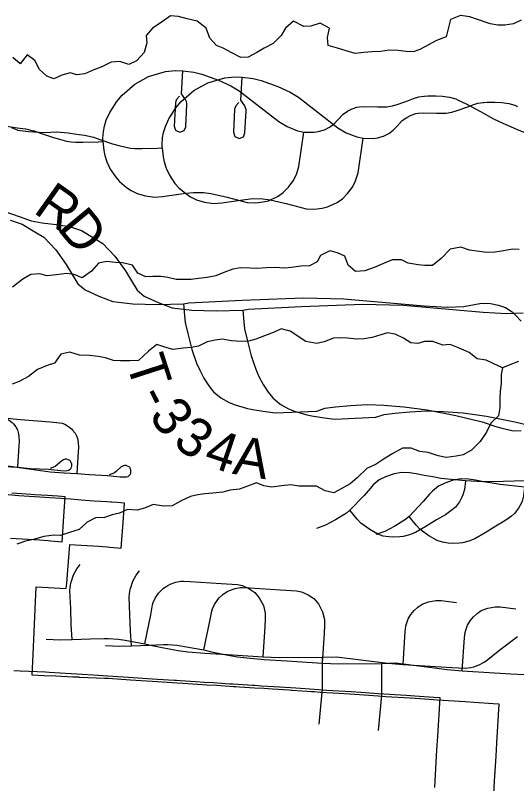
# Model space of a CAD drawing. Extents: x -38.2 to 41.9, y -4 to 24.9.
# Drawn here: x 7.758 to 8.49, y 18.257 to 19.38 of the extents above; entities that cross this region are included whole.
import ezdxf

# ---------------------------------------------------------------- set-up
doc = ezdxf.new("R2010")
doc.units = 0
for name, color, linetype in [('Default', 7, 'Continuous'), ('GM_X_County_Road', 7, 'Continuous'), ('GM_X_Minor_River', 7, 'Continuous'), ('GM_X_State_Location', 7, 'Continuous'), ('GM_X_Township_Road', 7, 'Continuous'), ('GM_X_Township_Road_Text', 7, 'Continuous')]:
    doc.layers.add(name, color=color, linetype=linetype)

msp = doc.modelspace()

# ---------------------------------------------------------------- linework, layer by layer
at = {"layer": 'Default'}
for points in [[(7.7507, 18.616), (7.7927, 18.6132), (7.8053, 18.6123), (7.8092, 18.6118), (7.8258, 18.6103), (7.8285, 18.6477), (7.8305, 18.6762), (7.8197, 18.677), (7.812, 18.6775), (7.8108, 18.6776), (7.8047, 18.678), (7.786, 18.6792), (7.7801, 18.6796), (7.7673, 18.6806), (7.7524, 18.6818)], [(8.3701, 18.2517), (8.3711, 18.2702), (8.3733, 18.3066), (8.3744, 18.326), (8.3778, 18.3826), (8.3688, 18.3832), (8.3412, 18.385), (8.3282, 18.3859), (8.2875, 18.3886), (8.2622, 18.3902), (8.2478, 18.3912), (8.2123, 18.3935), (8.2009, 18.3942), (8.167, 18.3965), (8.1594, 18.397), (8.135, 18.3986), (8.117, 18.3998), (8.1074, 18.4004), (8.1038, 18.4007), (8.0754, 18.4025), (8.0745, 18.4025), (8.0708, 18.4028), (8.0465, 18.4043), (8.0338, 18.4052), (8.0206, 18.406), (7.9984, 18.4074), (7.9932, 18.4078), (7.9895, 18.408), (7.9654, 18.4096), (7.9508, 18.4105), (7.9371, 18.4114), (7.9156, 18.4128), (7.9072, 18.4133), (7.8853, 18.4147), (7.8789, 18.4151), (7.8473, 18.4171), (7.8392, 18.4176), (7.8068, 18.4198), (7.8015, 18.42), (7.765, 18.4217), (7.7645, 18.4217), (7.7555, 18.4222)]]:
    msp.add_lwpolyline(points, dxfattribs=at)
at = {"layer": 'GM_X_County_Road'}
msp.add_lwpolyline([(8.4565, 18.2425), (8.4576, 18.261), (8.4598, 18.2974), (8.4609, 18.3168), (8.4643, 18.3734), (8.4553, 18.374), (8.4277, 18.3758), (8.4146, 18.3767), (8.374, 18.3794), (8.3487, 18.381), (8.3343, 18.382), (8.2987, 18.3843), (8.2874, 18.385), (8.2535, 18.3873), (8.2458, 18.3878), (8.2215, 18.3894), (8.2035, 18.3906), (8.1939, 18.3912), (8.1903, 18.3915), (8.1619, 18.3933), (8.161, 18.3934), (8.1573, 18.3936), (8.133, 18.3952), (8.1203, 18.396), (8.1071, 18.3968), (8.0848, 18.3983), (8.0797, 18.3986), (8.076, 18.3988), (8.0519, 18.4004), (8.0373, 18.4013), (8.0236, 18.4022), (8.002, 18.4036), (7.9937, 18.4041), (7.9718, 18.4055), (7.9654, 18.4059), (7.9338, 18.4079), (7.9257, 18.4084), (7.8933, 18.4106), (7.888, 18.4108), (7.8515, 18.4125), (7.851, 18.4126), (7.842, 18.413), (7.8415, 18.413), (7.8166, 18.4142), (7.7995, 18.4149), (7.7824, 18.4157), (7.7837, 18.4459), (7.7851, 18.4789), (7.7866, 18.512), (7.788, 18.5448), (7.8316, 18.5422), (7.833, 18.5499), (7.8344, 18.569), (7.8372, 18.6068), (7.8792, 18.604), (7.8917, 18.6031), (7.8957, 18.6026), (7.9123, 18.6011), (7.9149, 18.6385), (7.917, 18.667), (7.9061, 18.6678), (7.8985, 18.6683), (7.8973, 18.6684), (7.8912, 18.6688), (7.8725, 18.67), (7.8666, 18.6704), (7.8538, 18.6714), (7.8388, 18.6726), (7.824, 18.6737), (7.8078, 18.6748), (7.7932, 18.6758), (7.7779, 18.6768), (7.7629, 18.6778), (7.7625, 18.6779), (7.7473, 18.6789)], dxfattribs=at)
at = {"layer": 'GM_X_Minor_River'}
for points in [[(8.4962, 19.3727), (8.4849, 19.367), (8.4724, 19.3651), (8.4622, 19.3651), (8.4512, 19.367), (8.4327, 19.3735), (8.4213, 19.3773), (8.4077, 19.3795), (8.3933, 19.3735), (8.3895, 19.3598), (8.3869, 19.3484), (8.3729, 19.3428), (8.3619, 19.3371), (8.3483, 19.3299), (8.3385, 19.3265), (8.3282, 19.3268), (8.3169, 19.328), (8.3036, 19.3287), (8.2911, 19.3268), (8.2783, 19.3261), (8.2666, 19.3253), (8.2537, 19.3238), (8.2408, 19.3276), (8.2283, 19.3314), (8.2143, 19.3356), (8.2136, 19.347), (8.2162, 19.3606), (8.2026, 19.3682), (8.1893, 19.364), (8.1791, 19.3633), (8.164, 19.3709), (8.1519, 19.361), (8.1458, 19.35), (8.1341, 19.3382), (8.1212, 19.3318), (8.1103, 19.3254), (8.0974, 19.3185), (8.0868, 19.3182), (8.0739, 19.3246), (8.0611, 19.3314), (8.0512, 19.3356), (8.0417, 19.3462), (8.0361, 19.361), (8.0232, 19.3709), (8.0084, 19.3743), (7.9959, 19.3777), (7.9842, 19.3788), (7.9691, 19.3682), (7.9581, 19.3607), (7.9487, 19.35), (7.9494, 19.3394), (7.9456, 19.3254), (7.9343, 19.3133), (7.9233, 19.3076), (7.9104, 19.3121), (7.8976, 19.3114), (7.884, 19.3042), (7.8722, 19.3), (7.859, 19.2943), (7.8476, 19.2928), (7.8378, 19.2958), (7.8253, 19.292), (7.8136, 19.2867), (7.8034, 19.2905), (7.7928, 19.3004), (7.7859, 19.3137), (7.775, 19.322), (7.7647, 19.3087), (7.7541, 19.3182)], [(8.4934, 19.0374), (8.4835, 19.0378), (8.4703, 19.0355), (8.4582, 19.0336), (8.446, 19.0329), (8.4351, 19.0344), (8.4207, 19.0363), (8.4082, 19.0409), (8.3927, 19.0378), (8.3794, 19.0246), (8.3666, 19.0139), (8.3556, 19.0139), (8.3458, 19.0151), (8.3314, 19.0174), (8.3215, 19.0223), (8.3079, 19.0223), (8.2954, 19.017), (8.2814, 19.0113), (8.2682, 19.0064), (8.2546, 19.0056), (8.2436, 19.0147), (8.2387, 19.0276), (8.2281, 19.0326), (8.2167, 19.0356), (8.2035, 19.0288), (8.1986, 19.0193), (8.1872, 19.0136), (8.1743, 19.0132), (8.1611, 19.011), (8.1505, 19.0102), (8.1372, 19.0113), (8.1244, 19.0106), (8.1104, 19.0098), (8.1005, 19.0102), (8.0862, 19.0106), (8.0752, 19.0087), (8.0619, 19.0038), (8.0506, 18.9992), (8.0377, 18.9966), (8.0249, 18.9951), (8.0143, 18.9939), (8.0033, 18.9939), (7.9927, 18.9936), (7.9802, 18.9966), (7.97, 18.9981), (7.9586, 18.9981), (7.948, 18.9978), (7.9363, 19.0031), (7.9287, 19.0144), (7.9143, 19.0179), (7.9037, 19.0186), (7.8913, 19.0198), (7.8791, 19.0175), (7.8686, 19.0057), (7.8553, 18.9963), (7.8436, 19.0008), (7.8322, 19.0027), (7.8175, 19.0004), (7.8038, 18.9989), (7.7932, 19.002), (7.78, 19.0008), (7.7683, 18.994), (7.7535, 18.9823)], [(8.4923, 18.8739), (8.4821, 18.8698), (8.4692, 18.8648), (8.4556, 18.8709), (8.445, 18.8759), (8.4321, 18.8778), (8.4204, 18.8872), (8.4049, 18.8937), (8.3924, 18.8986), (8.3818, 18.8979), (8.3674, 18.9032), (8.3553, 18.9032), (8.3454, 18.9002), (8.3352, 18.9013), (8.3246, 18.9078), (8.3121, 18.9138), (8.3012, 18.9157), (8.2913, 18.9127), (8.2788, 18.9089), (8.2671, 18.907), (8.2557, 18.9066), (8.2425, 18.9078), (8.2323, 18.9085), (8.2221, 18.9082), (8.2084, 18.9025), (8.1978, 18.9002), (8.1819, 18.9032), (8.1592, 18.9184), (8.146, 18.9215), (8.1358, 18.9169), (8.1214, 18.9112), (8.1089, 18.9067), (8.0983, 18.9036), (8.0873, 18.9029), (8.073, 18.904), (8.0601, 18.9063), (8.0495, 18.9052), (8.0378, 18.9025), (8.0249, 18.8965), (8.0151, 18.8942), (8.0026, 18.8934), (7.9874, 18.8915), (7.9746, 18.8953), (7.9643, 18.8988), (7.9519, 18.8889), (7.9375, 18.8756), (7.9246, 18.8749), (7.9114, 18.8749), (7.9008, 18.8753), (7.8894, 18.8791), (7.8788, 18.8813), (7.866, 18.8825), (7.8512, 18.8832), (7.8372, 18.8874), (7.8239, 18.8844), (7.8149, 18.8715), (7.8039, 18.8681), (7.7899, 18.862), (7.777, 18.8518), (7.763, 18.8446), (7.7532, 18.8408)], [(8.4692, 18.8648), (8.4673, 18.855), (8.4669, 18.8425), (8.4658, 18.8303), (8.4651, 18.8205), (8.4651, 18.8064), (8.4632, 18.7943), (8.4522, 18.7837), (8.4458, 18.7708), (8.4363, 18.7571), (8.4238, 18.7446), (8.4117, 18.7378), (8.4015, 18.7355), (8.3868, 18.7336), (8.375, 18.7359), (8.3603, 18.7408), (8.3485, 18.7424), (8.3357, 18.7473), (8.3232, 18.7473), (8.3088, 18.7397), (8.2978, 18.7329), (8.2846, 18.7238), (8.271, 18.7177), (8.2566, 18.7041), (8.2464, 18.6954), (8.2335, 18.6878), (8.2225, 18.6821), (8.2101, 18.6851), (8.1972, 18.692), (8.1851, 18.6916), (8.1714, 18.692), (8.1601, 18.6939), (8.1465, 18.6924), (8.1321, 18.6901), (8.1207, 18.6924), (8.1098, 18.6969), (8.0965, 18.6916), (8.0848, 18.6875), (8.0712, 18.6859), (8.0606, 18.6829), (8.0462, 18.6814), (8.0341, 18.6806), (8.0239, 18.6791), (8.0133, 18.6769), (8, 18.6704), (7.9868, 18.6632), (7.9739, 18.6625), (7.9591, 18.6651), (7.9463, 18.6598), (7.9357, 18.6568), (7.9213, 18.6579), (7.9096, 18.6522), (7.899, 18.65), (7.8876, 18.6462), (7.8748, 18.6454), (7.8623, 18.6394), (7.8509, 18.6284), (7.8365, 18.6242), (7.8237, 18.6197), (7.8138, 18.6204), (7.7991, 18.6182), (7.7839, 18.614), (7.7722, 18.6113), (7.7597, 18.6072)]]:
    msp.add_lwpolyline(points, dxfattribs=at)
at = {"layer": 'GM_X_State_Location'}
msp.add_line((8.2927, 18.3936), (8.2927, 18.4328), dxfattribs=at)
for points in [[(7.8698, 19.2019), (7.8717, 19.2015), (7.8809, 19.1982), (7.8996, 19.1921), (7.9086, 19.1894), (7.9188, 19.1868), (7.9256, 19.1856), (7.9322, 19.1851), (7.9429, 19.185), (7.9649, 19.1855), (7.9719, 19.1862), (7.9719, 19.1909), (7.9727, 19.2005), (7.9741, 19.2083), (7.9768, 19.2171), (7.982, 19.2285), (7.9921, 19.2444), (7.9999, 19.2538), (8.0184, 19.27), (8.0388, 19.2809), (8.0635, 19.2881), (8.0782, 19.2896), (8.0888, 19.2893), (8.1047, 19.2875), (8.1166, 19.2844), (8.1408, 19.2757), (8.159, 19.2675), (8.1709, 19.2602), (8.2288, 19.2154), (8.2409, 19.2079), (8.2562, 19.2019), (8.2654, 19.2), (8.2804, 19.1999), (8.2864, 19.2006), (8.2954, 19.2032), (8.303, 19.2072), (8.3092, 19.2117), (8.315, 19.2177), (8.3227, 19.2262), (8.3293, 19.2304), (8.3357, 19.2338), (8.3425, 19.236), (8.346, 19.2367), (8.3532, 19.2371), (8.373, 19.2367), (8.3866, 19.2367), (8.3949, 19.238), (8.403, 19.2404), (8.4185, 19.2461), (8.4258, 19.2488), (8.4332, 19.2512), (8.4407, 19.2522), (8.4417, 19.2523)], [(8.084, 19.2524), (8.0795, 19.2472), (8.0784, 19.2449), (8.0779, 19.2425), (8.076, 19.2088), (8.0781, 19.2024), (8.0845, 19.1995), (8.0906, 19.2023), (8.0928, 19.2077), (8.0946, 19.2403), (8.0945, 19.2418), (8.0939, 19.2447), (8.0927, 19.2475), (8.087, 19.2557), (8.0888, 19.2893)], [(8.4417, 19.2523), (8.4465, 19.2526), (8.458, 19.2526), (8.468, 19.2522), (8.4781, 19.2506), (8.4872, 19.2482), (8.4908, 19.2465)], [(7.7518, 19.2157), (7.7613, 19.212), (7.7766, 19.2097), (7.8, 19.2084), (7.8184, 19.2096), (7.8347, 19.2081), (7.8469, 19.206), (7.8587, 19.2047), (7.8698, 19.2019)], [(7.9719, 19.1862), (7.9733, 19.173), (7.9749, 19.1654), (7.9778, 19.1562), (7.9827, 19.1459), (7.9907, 19.134), (7.9963, 19.1276), (8.0064, 19.1191), (8.0133, 19.1145), (8.022, 19.1103), (8.0339, 19.1066), (8.0477, 19.1049), (8.0591, 19.1055), (8.0896, 19.1101), (8.1038, 19.1118), (8.119, 19.1117), (8.1298, 19.1101), (8.1533, 19.1046), (8.1825, 19.0971), (8.1946, 19.0964), (8.2059, 19.0978), (8.2135, 19.0996), (8.2277, 19.1064), (8.2353, 19.1117), (8.2429, 19.1192), (8.2498, 19.1288), (8.2545, 19.1377), (8.2581, 19.1495), (8.2654, 19.2)], [(7.7421, 19.093), (7.7634, 19.0855), (7.7809, 19.0793), (7.797, 19.0766), (7.8174, 19.0741), (7.8366, 19.0712), (7.854, 19.0653), (7.8728, 19.0542), (7.8855, 19.0461), (7.9031, 19.028), (7.9185, 19.0063), (7.9257, 18.9944), (7.9353, 18.9781), (7.9458, 18.9694), (7.966, 18.9603), (7.9864, 18.9525), (8.0154, 18.9491), (8.0516, 18.9479), (8.0896, 18.9489), (8.0974, 18.9503), (8.1754, 18.9544), (8.2649, 18.9576), (8.3239, 18.9563), (8.441, 18.9462), (8.475, 18.9439), (8.4993, 18.9452)], [(8.0896, 18.9489), (8.0911, 18.9318), (8.0922, 18.9218), (8.0961, 18.9057), (8.102, 18.8822), (8.1087, 18.8625), (8.1134, 18.8522), (8.1196, 18.8402), (8.1267, 18.8292), (8.1337, 18.8206), (8.1444, 18.8117), (8.1566, 18.8047), (8.1653, 18.8013), (8.1833, 18.7962), (8.1907, 18.7947), (8.2058, 18.7922), (8.2236, 18.7898), (8.2843, 18.7924), (8.2962, 18.7963), (8.3118, 18.7983), (8.3335, 18.8003), (8.3584, 18.8017), (8.3824, 18.8007), (8.4117, 18.7987), (8.4457, 18.794), (8.4873, 18.7857), (8.5259, 18.7767)], [(7.7056, 18.7974), (7.7363, 18.7927), (7.7545, 18.7903), (7.7651, 18.7894), (7.8083, 18.7859), (7.8182, 18.7849), (7.8258, 18.7837), (7.8299, 18.7823), (7.8351, 18.7792), (7.8394, 18.7757), (7.8413, 18.7738), (7.8449, 18.7691), (7.8471, 18.7651), (7.8484, 18.7612), (7.8494, 18.7559), (7.8497, 18.7478), (7.8492, 18.7418), (7.8473, 18.7104)], [(7.7466, 18.7216), (7.7666, 18.7187), (7.8083, 18.7129), (7.8289, 18.7114), (7.8473, 18.7104), (7.866, 18.7087), (7.8922, 18.7073), (7.9105, 18.7056), (7.918, 18.7052), (7.9201, 18.7053), (7.9222, 18.706), (7.924, 18.7073), (7.9254, 18.709), (7.9262, 18.7107), (7.9264, 18.712), (7.9264, 18.7146), (7.9257, 18.7171), (7.9246, 18.7193), (7.9237, 18.7201), (7.9216, 18.7212), (7.9193, 18.7219), (7.9169, 18.7219), (7.9158, 18.7217), (7.9145, 18.7212), (7.9122, 18.7198), (7.9052, 18.7137), (7.9022, 18.7115), (7.8989, 18.7098), (7.8948, 18.7082)], [(8.5013, 18.6903), (8.4657, 18.694), (8.454, 18.696), (8.4412, 18.6983), (8.4295, 18.7004), (8.4195, 18.7021), (8.4087, 18.7024), (8.3971, 18.7008), (8.3848, 18.6964), (8.3755, 18.6917), (8.3668, 18.6847), (8.3626, 18.6799), (8.3534, 18.6692), (8.3326, 18.6473), (8.3274, 18.6433), (8.3116, 18.6334), (8.2971, 18.6257), (8.2841, 18.621)], [(8.5013, 18.6903), (8.4998, 18.6778), (8.4978, 18.6701), (8.4964, 18.6664), (8.4926, 18.6595), (8.4867, 18.6518), (8.4821, 18.6479), (8.4725, 18.641), (8.4594, 18.6333), (8.4437, 18.6237), (8.4285, 18.6149), (8.4197, 18.6115), (8.4105, 18.6092), (8.4058, 18.6085), (8.3964, 18.608), (8.3897, 18.6084), (8.3815, 18.6099), (8.3735, 18.6125), (8.3616, 18.6192), (8.3486, 18.6286), (8.3432, 18.6346), (8.3326, 18.6473)], [(7.9273, 18.4588), (7.9257, 18.4798), (7.9249, 18.5037), (7.9239, 18.5301), (7.9242, 18.5342), (7.9248, 18.5384), (7.9257, 18.5424), (7.9292, 18.553), (7.934, 18.5616), (7.939, 18.5682)], [(8.0331, 18.4525), (8.0417, 18.4948), (8.0445, 18.5091), (8.0456, 18.5125), (8.0485, 18.5191), (8.0533, 18.5263), (8.0555, 18.5289), (8.0605, 18.5335), (8.067, 18.5378), (8.0702, 18.5395), (8.0786, 18.5425), (8.0857, 18.5437), (8.0896, 18.5438), (8.0995, 18.5434), (8.1448, 18.5404), (8.1682, 18.5391), (8.1756, 18.5374), (8.1851, 18.5333), (8.1937, 18.5275), (8.2004, 18.5197), (8.2064, 18.5082), (8.2089, 18.497), (8.2089, 18.4881), (8.2085, 18.4772), (8.2057, 18.4334)], [(8.4103, 18.4222), (8.4134, 18.4705), (8.4144, 18.4779), (8.4153, 18.4816), (8.418, 18.4886), (8.4218, 18.495), (8.4265, 18.501), (8.4319, 18.506), (8.4381, 18.51), (8.4474, 18.5138), (8.4584, 18.5156), (8.4658, 18.5154), (8.4886, 18.5125)], [(7.8892, 18.4591), (7.9096, 18.4582), (7.9273, 18.4588), (7.9536, 18.4596), (7.9738, 18.4604), (7.9803, 18.4603), (7.994, 18.4593), (8.0047, 18.4574), (8.0331, 18.4525), (8.0441, 18.4497), (8.0563, 18.4475), (8.071, 18.4446), (8.0819, 18.4426), (8.0958, 18.4408), (8.121, 18.4387), (8.1539, 18.4366), (8.2057, 18.4334), (8.23, 18.4325), (8.2927, 18.4328), (8.313, 18.4335), (8.3882, 18.4239), (8.4103, 18.4222), (8.4813, 18.4177), (8.5012, 18.4168)], [(8.2878, 18.3347), (8.2927, 18.3867), (8.2927, 18.3936)]]:
    msp.add_lwpolyline(points, dxfattribs=at)
at = {"layer": 'GM_X_Township_Road'}
msp.add_line((8.2062, 18.4028), (8.2062, 18.442), dxfattribs=at)
for points in [[(7.7834, 19.2111), (7.7852, 19.2107), (7.7945, 19.2074), (7.8131, 19.2013), (7.8221, 19.1986), (7.8323, 19.196), (7.8391, 19.1948), (7.8457, 19.1943), (7.8564, 19.1942), (7.8784, 19.1947), (7.8855, 19.1954), (7.8854, 19.2001), (7.8862, 19.2097), (7.8876, 19.2175), (7.8903, 19.2263), (7.8955, 19.2377), (7.9056, 19.2536), (7.9134, 19.263), (7.9319, 19.2792), (7.9523, 19.2901), (7.977, 19.2973), (7.9917, 19.2988), (8.0023, 19.2985), (8.0183, 19.2967), (8.0301, 19.2936), (8.0543, 19.2849), (8.0725, 19.2767), (8.0844, 19.2694), (8.1423, 19.2246), (8.1544, 19.2171), (8.1698, 19.2111), (8.1789, 19.2091), (8.194, 19.2091), (8.1999, 19.2098), (8.209, 19.2124), (8.2165, 19.2164), (8.2227, 19.2208), (8.2285, 19.2269), (8.2362, 19.2353), (8.2428, 19.2396), (8.2493, 19.243), (8.2561, 19.2452), (8.2596, 19.2459), (8.2667, 19.2463), (8.2865, 19.2459), (8.3001, 19.2459), (8.3085, 19.2472), (8.3165, 19.2496), (8.332, 19.2553), (8.3393, 19.258), (8.3467, 19.2604), (8.3542, 19.2614), (8.3552, 19.2615)], [(7.9975, 19.2616), (7.993, 19.2564), (7.9919, 19.2541), (7.9914, 19.2516), (7.9896, 19.2179), (7.9917, 19.2116), (7.998, 19.2087), (8.0042, 19.2115), (8.0064, 19.2169), (8.0081, 19.2494), (8.008, 19.2509), (8.0074, 19.2539), (8.0062, 19.2566), (8.0005, 19.2649), (8.0023, 19.2985)], [(8.3552, 19.2615), (8.36, 19.2618), (8.3715, 19.2618), (8.3815, 19.2614), (8.3917, 19.2598), (8.4008, 19.2574), (8.4043, 19.2557)], [(8.4043, 19.2557), (8.4158, 19.2502), (8.4367, 19.2393), (8.456, 19.2285), (8.4695, 19.222), (8.4851, 19.2152)], [(7.6653, 19.2248), (7.6748, 19.2212), (7.6901, 19.2189), (7.7135, 19.2176), (7.7319, 19.2188), (7.7482, 19.2173), (7.7604, 19.2152), (7.7723, 19.2139), (7.7834, 19.2111)], [(8.4851, 19.2152), (8.4907, 19.2128), (8.5065, 19.2063), (8.5172, 19.2033), (8.5276, 19.2028), (8.539, 19.2031), (8.554, 19.2057), (8.5811, 19.2148)], [(7.8855, 19.1954), (7.8868, 19.1822), (7.8885, 19.1746), (7.8913, 19.1654), (7.8962, 19.1551), (7.9042, 19.1432), (7.9098, 19.1368), (7.9199, 19.1282), (7.9268, 19.1237), (7.9355, 19.1195), (7.9475, 19.1158), (7.9612, 19.1141), (7.9726, 19.1147), (8.0032, 19.1193), (8.0174, 19.121), (8.0325, 19.1209), (8.0433, 19.1193), (8.0668, 19.1138), (8.0961, 19.1063), (8.1081, 19.1055), (8.1195, 19.107), (8.1271, 19.1088), (8.1413, 19.1156), (8.1488, 19.1209), (8.1565, 19.1284), (8.1633, 19.138), (8.168, 19.1469), (8.1717, 19.1586), (8.1789, 19.2091)], [(7.7501, 19.0804), (7.7676, 19.0745), (7.7863, 19.0634), (7.799, 19.0553), (7.8167, 19.0371), (7.832, 19.0155), (7.8392, 19.0036), (7.8488, 18.9873), (7.8594, 18.9786), (7.8795, 18.9695), (7.8999, 18.9617), (7.929, 18.9583), (7.9651, 18.9571), (8.0032, 18.9581), (8.0109, 18.9595), (8.0889, 18.9636), (8.1784, 18.9668), (8.2374, 18.9654), (8.3545, 18.9554), (8.3885, 18.9531), (8.4128, 18.9544), (8.4361, 18.9584), (8.4446, 18.9591), (8.4513, 18.9588), (8.4634, 18.9561), (8.4733, 18.9526), (8.4832, 18.9467), (8.4885, 18.9411), (8.4964, 18.9329)], [(8.0032, 18.9581), (8.0046, 18.941), (8.0057, 18.931), (8.0096, 18.9149), (8.0155, 18.8914), (8.0222, 18.8717), (8.0269, 18.8614), (8.0331, 18.8494), (8.0403, 18.8384), (8.0472, 18.8298), (8.0579, 18.8209), (8.0701, 18.8139), (8.0788, 18.8105), (8.0968, 18.8054), (8.1042, 18.8039), (8.1193, 18.8013), (8.1372, 18.799), (8.1978, 18.8015), (8.2097, 18.8055), (8.2254, 18.8075), (8.247, 18.8095), (8.272, 18.8109), (8.2959, 18.8099), (8.3252, 18.8079), (8.3592, 18.8032), (8.4008, 18.7949), (8.4394, 18.7859), (8.4594, 18.7792), (8.4666, 18.7769), (8.4846, 18.7725), (8.4961, 18.7731)], [(7.6191, 18.8066), (7.6498, 18.8018), (7.668, 18.7995), (7.6787, 18.7986), (7.7218, 18.7951), (7.7317, 18.7941), (7.7394, 18.7928), (7.7434, 18.7914), (7.7486, 18.7884), (7.7529, 18.7849), (7.7549, 18.783), (7.7584, 18.7783), (7.7606, 18.7743), (7.7619, 18.7704), (7.7629, 18.765), (7.7632, 18.757), (7.7627, 18.751), (7.7608, 18.7196)], [(7.7424, 18.7206), (7.7608, 18.7196), (7.7795, 18.7178), (7.8058, 18.7165), (7.8241, 18.7148), (7.8315, 18.7144), (7.8337, 18.7145), (7.8357, 18.7152), (7.8376, 18.7165), (7.839, 18.7181), (7.8398, 18.7199), (7.84, 18.7211), (7.8399, 18.7237), (7.8393, 18.7263), (7.8381, 18.7285), (7.8372, 18.7292), (7.8351, 18.7304), (7.8328, 18.731), (7.8304, 18.7311), (7.8293, 18.7309), (7.828, 18.7304), (7.8257, 18.7289), (7.8187, 18.7229), (7.8157, 18.7207), (7.8124, 18.719), (7.8083, 18.7174)], [(8.5015, 18.6998), (8.4704, 18.6984), (8.4405, 18.6982), (8.4148, 18.6995), (8.3792, 18.7032), (8.3675, 18.7052), (8.3547, 18.7075), (8.3431, 18.7096), (8.333, 18.7113), (8.3222, 18.7116), (8.3107, 18.71), (8.2983, 18.7056), (8.289, 18.7009), (8.2804, 18.6939), (8.2761, 18.6891), (8.2669, 18.6784), (8.2462, 18.6565), (8.241, 18.6525), (8.2252, 18.6426), (8.2106, 18.6349), (8.1976, 18.6302)], [(8.4148, 18.6995), (8.4134, 18.687), (8.4113, 18.6793), (8.4099, 18.6756), (8.4062, 18.6687), (8.4002, 18.661), (8.3956, 18.6571), (8.386, 18.6501), (8.3729, 18.6425), (8.3572, 18.6329), (8.342, 18.6241), (8.3332, 18.6206), (8.324, 18.6184), (8.3193, 18.6177), (8.3099, 18.6172), (8.3032, 18.6176), (8.295, 18.619), (8.287, 18.6217), (8.2751, 18.6283), (8.2621, 18.6378), (8.2567, 18.6438), (8.2462, 18.6565)], [(7.8408, 18.468), (7.8392, 18.489), (7.8384, 18.5129), (7.8374, 18.5393), (7.8377, 18.5434), (7.8383, 18.5476), (7.8392, 18.5516), (7.8427, 18.5622), (7.8475, 18.5708), (7.8525, 18.5774)], [(7.9466, 18.4617), (7.9553, 18.504), (7.958, 18.5183), (7.9591, 18.5217), (7.962, 18.5282), (7.9668, 18.5355), (7.969, 18.5381), (7.974, 18.5426), (7.9805, 18.5469), (7.9837, 18.5487), (7.9921, 18.5517), (7.9992, 18.5528), (8.0031, 18.553), (8.0131, 18.5526), (8.0583, 18.5496), (8.0818, 18.5483), (8.0892, 18.5466), (8.0987, 18.5425), (8.1072, 18.5367), (8.1139, 18.5289), (8.12, 18.5173), (8.1224, 18.5062), (8.1225, 18.4973), (8.122, 18.4864), (8.1192, 18.4426)], [(8.3238, 18.4313), (8.327, 18.4797), (8.3279, 18.4871), (8.3288, 18.4908), (8.3315, 18.4978), (8.3353, 18.5042), (8.34, 18.5102), (8.3455, 18.5152), (8.3516, 18.5192), (8.3609, 18.5229), (8.3719, 18.5248), (8.3794, 18.5246), (8.4021, 18.5217)], [(7.8028, 18.4683), (7.8231, 18.4674), (7.8408, 18.468), (7.8671, 18.4688), (7.8873, 18.4695), (7.8938, 18.4695), (7.9076, 18.4685), (7.9182, 18.4666), (7.9466, 18.4617), (7.9576, 18.4589), (7.9698, 18.4567), (7.9845, 18.4538), (7.9955, 18.4518), (8.0094, 18.45), (8.0345, 18.4479), (8.0674, 18.4458), (8.1192, 18.4426), (8.1435, 18.4417), (8.2062, 18.442), (8.2265, 18.4427), (8.3017, 18.4331), (8.3238, 18.4313), (8.3949, 18.4269), (8.4147, 18.426), (8.423, 18.427), (8.4271, 18.4279), (8.435, 18.4307), (8.4424, 18.4345), (8.4459, 18.4369), (8.4673, 18.454), (8.4909, 18.4721)], [(8.2013, 18.3439), (8.2062, 18.3959), (8.2062, 18.4028)]]:
    msp.add_lwpolyline(points, dxfattribs=at)

# ---------------------------------------------------------------- texts
at = {"layer": 'GM_X_Township_Road_Text'}
for s, rotation, p in [('R', 324.752, (7.7822, 19.0925)), ('D', 309.5141, (7.8173, 19.0683)), ('T', 287.9213, (7.9187, 18.8733)), ('-', 296.9412, (7.9355, 18.8238)), ('3', 306.3825, (7.9514, 18.7944)), ('3', 324.0178, (7.9857, 18.7528)), ('4', 341.4229, (8.0307, 18.7236)), ('A', 350.5221, (8.0734, 18.7101))]:
    msp.add_text(s, height=0.0568, rotation=rotation, dxfattribs=at).set_placement(p)

doc.saveas('drawing.dxf')
